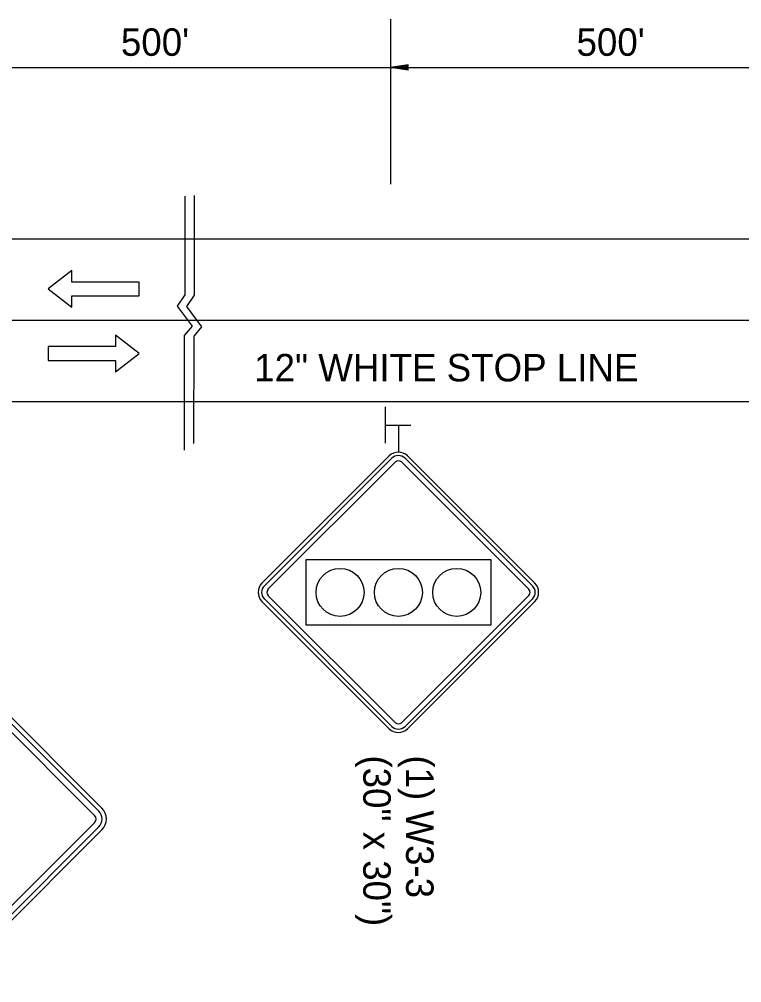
# Model space of a CAD drawing. Extents: x 1930579 to 1939784, y 596179 to 597522.
# Drawn here: x 1937952 to 1938109.9, y 596778.8 to 596989.5 of the extents above; entities that cross this region are included whole.
import ezdxf

# ---------------------------------------------------------------- set-up
doc = ezdxf.new("R2010")
doc.units = 0
for name, color, linetype in [('Default', 7, 'Continuous'), ('P_TC_Signs_Permanent', 7, 'Continuous'), ('P_TC_Signs_Temporary', 7, 'Continuous'), ('R_Annotation', 7, 'Continuous'), ('R_Striping', 7, 'Continuous')]:
    doc.layers.add(name, color=color, linetype=linetype)

msp = doc.modelspace()

# ---------------------------------------------------------------- linework, layer by layer
at = {"layer": 'Default'}
for p, q in [((1938033.12, 596989.48), (1938033.12, 596953.45)), ((1937934.22, 596978.92), (1938033.98, 596978.92)), ((1938036.96, 596979.49), (1938033.12, 596978.92)), ((1938033.12, 596978.92), (1938134.25, 596978.92)), ((1938036.96, 596978.34), (1938033.12, 596978.92)), ((1938036.96, 596979.4), (1938033.76, 596978.92)), ((1938036.96, 596978.44), (1938033.76, 596978.92)), ((1938036.96, 596979.3), (1938034.42, 596978.92)), ((1938036.96, 596978.53), (1938034.42, 596978.92)), ((1938036.96, 596979.2), (1938035.06, 596978.92)), ((1938036.96, 596978.63), (1938035.06, 596978.92)), ((1938036.96, 596979.1), (1938035.71, 596978.92)), ((1938036.96, 596978.73), (1938035.71, 596978.92)), ((1938036.96, 596979.01), (1938036.35, 596978.92)), ((1938036.96, 596978.83), (1938036.35, 596978.92)), ((1938036.96, 596978.34), (1938036.96, 596979.49)), ((1937601.26, 596941.48), (1938703.26, 596941.48)), ((1937499.1, 596923.69), (1938703.26, 596923.69)), ((1937601.26, 596905.9), (1938703.26, 596905.9)), ((1938032.01, 596896.77), (1938032.01, 596904.77)), ((1938032.13, 596900.75), (1938037.59, 596900.75))]:
    msp.add_line(p, q, dxfattribs=at)
for points in [[(1937988.19, 596950.77), (1937988.19, 596929.24), (1937986.53, 596926.77), (1937989.77, 596922.34), (1937988.06, 596920.3), (1937988.06, 596895.27)], [(1937990.24, 596950.96), (1937990.24, 596929.16), (1937988.57, 596926.69), (1937991.81, 596922.26), (1937990.11, 596920.21), (1937990.1, 596896.71)]]:
    msp.add_lwpolyline(points, dxfattribs=at)
at = {"layer": 'P_TC_Signs_Permanent'}
for p, q in [((1938005.03, 596866.16), (1938032.87, 596894.01)), ((1938005.56, 596865.63), (1938033.4, 596893.48)), ((1938034.2, 596892.68), (1938006.35, 596864.84)), ((1938063.37, 596864.84), (1938035.52, 596892.68)), ((1938036.32, 596893.48), (1938064.16, 596865.63)), ((1938036.85, 596894.01), (1938064.69, 596866.16)), ((1938006.35, 596863.51), (1938034.2, 596835.67)), ((1938035.52, 596835.67), (1938063.37, 596863.51)), ((1938032.87, 596834.34), (1938005.03, 596862.19)), ((1938033.4, 596834.87), (1938005.56, 596862.72)), ((1938064.16, 596862.72), (1938036.32, 596834.87)), ((1938064.69, 596862.19), (1938036.85, 596834.34))]:
    msp.add_line(p, q, dxfattribs=at)
msp.add_lwpolyline([(1938014.61, 596871.3), (1938014.61, 596857.05), (1938055.11, 596857.05), (1938055.11, 596871.3)], close=True, dxfattribs=at)
for centre in [(1938022.11, 596864.17), (1938034.86, 596864.17), (1938047.61, 596864.17)]:
    msp.add_circle(centre, 5.25, dxfattribs=at)
for centre, radius, start, end in [((1938034.86, 596892.02), 2.81, 45, 135), ((1938034.86, 596892.02), 2.06, 45, 135), ((1938034.86, 596892.02), 0.938, 45, 135), ((1938007.02, 596864.17), 2.81, 135, 225), ((1938007.02, 596864.17), 2.06, 135, 225), ((1938062.7, 596864.17), 2.06, 315, 45), ((1938062.7, 596864.17), 2.81, 315, 45), ((1938007.02, 596864.17), 0.938, 135, 225), ((1938062.7, 596864.17), 0.938, 315, 45), ((1938034.86, 596836.33), 0.938, 225, 315), ((1938034.86, 596836.33), 2.81, 225, 315), ((1938034.86, 596836.33), 2.06, 225, 315)]:
    msp.add_arc(centre, radius, start, end, dxfattribs=at)
at = {"layer": 'P_TC_Signs_Temporary'}
for p, q in [((1937936.63, 596850.41), (1937970.04, 596816.99)), ((1937935.04, 596848.81), (1937968.45, 596815.4)), ((1937935.97, 596849.74), (1937969.38, 596816.33)), ((1937968.45, 596813.81), (1937935.04, 596780.4)), ((1937969.38, 596812.88), (1937935.97, 596779.47)), ((1937970.04, 596812.22), (1937936.63, 596778.81))]:
    msp.add_line(p, q, dxfattribs=at)
for radius in [3.38, 1.13, 2.44]:
    msp.add_arc((1937967.66, 596814.61), radius, 315, 45, dxfattribs=at)
at = {"layer": 'R_Annotation'}
msp.add_line((1938034.86, 596900.75), (1938034.86, 596894.83), dxfattribs=at)
at = {"layer": 'R_Striping'}
for points in [[(1937963.51, 596934.53), (1937958.32, 596930.53), (1937963.51, 596926.53), (1937963.51, 596929.03), (1937978.22, 596929.03), (1937978.22, 596932.03), (1937963.51, 596932.03)], [(1937973.03, 596912.4), (1937978.22, 596916.4), (1937973.03, 596920.4), (1937973.03, 596917.9), (1937958.32, 596917.9), (1937958.32, 596914.9), (1937973.03, 596914.9)]]:
    msp.add_lwpolyline(points, close=True, dxfattribs=at)

# ---------------------------------------------------------------- texts
at = {"layer": 'Default'}
for s, height, p in [("500'", 6, (1937974.2, 596981.49)), ("500'", 6, (1938073.79, 596981.49)), ('12" WHITE STOP LINE', 5.9996, (1938003.34, 596910.3))]:
    msp.add_text(s, height=height, rotation=360, dxfattribs=at).set_placement(p)
at = {"layer": 'R_Annotation'}
for s, height, p in [('(30" x 30")', 5.9996, (1938027.18, 596828.52)), ('(1) W3-3', 6, (1938036.54, 596828.52))]:
    msp.add_text(s, height=height, rotation=270, dxfattribs=at).set_placement(p)

doc.saveas('drawing.dxf')
